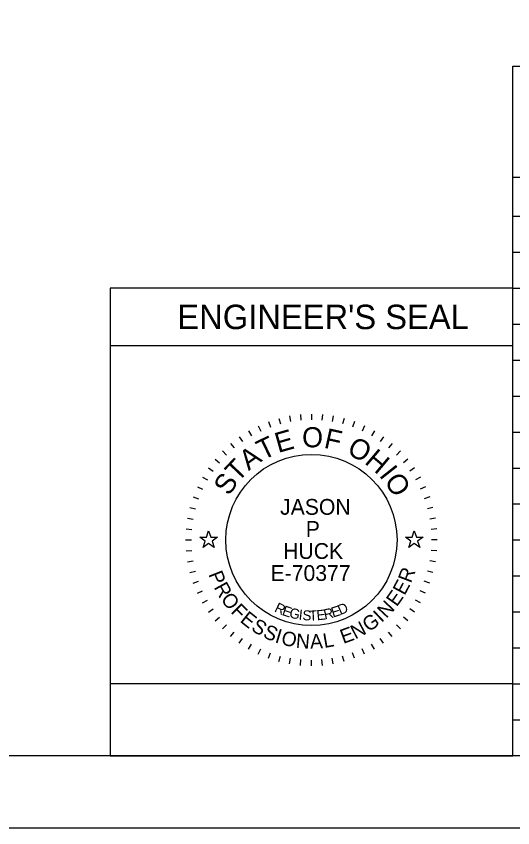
# Model space of a CAD drawing. Extents: x -1.8 to 75.7, y -2 to 25.
# Drawn here: x 48.4 to 51.85, y 1.61 to 7.25 of the extents above; entities that cross this region are included whole.
import ezdxf

# ---------------------------------------------------------------- set-up
doc = ezdxf.new("R2010")
doc.units = 0
for name, color, linetype in [('Default', 7, 'Continuous'), ('SH_Border', 7, 'Continuous'), ('SH_Cut_Line', 7, 'Continuous'), ('SH_Data', 7, 'Continuous')]:
    doc.layers.add(name, color=color, linetype=linetype)

msp = doc.modelspace()

# ---------------------------------------------------------------- linework, layer by layer
at = {"layer": 'Default'}
for points in [[(49.6738, 3.632), (49.7207, 3.632), (49.7352, 3.6766), (49.7497, 3.632), (49.7965, 3.632), (49.7587, 3.6045), (49.7731, 3.5599), (49.7352, 3.5874), (49.6972, 3.5599), (49.7117, 3.6045)], [(51.1038, 3.632), (51.1507, 3.632), (51.1652, 3.6766), (51.1797, 3.632), (51.2265, 3.632), (51.1887, 3.6045), (51.2031, 3.5599), (51.1652, 3.5874), (51.1272, 3.5599), (51.1417, 3.6045)]]:
    msp.add_lwpolyline(points, close=True, dxfattribs=at)
at = {"layer": 'SH_Border'}
msp.add_lwpolyline([(43.2002, 23.1121), (75.2002, 23.1121), (75.2002, 2.1121), (43.2002, 2.1121)], close=True, dxfattribs=at)
at = {"layer": 'SH_Cut_Line'}
msp.add_lwpolyline([(41.7002, 1.6121), (75.7002, 1.6121), (75.7002, 23.6121), (41.7002, 23.6121)], close=True, dxfattribs=at)
at = {"layer": 'SH_Data'}
for p, q in [((51.8502, 6.9038), (65.3002, 6.9038)), ((51.8502, 2.1121), (51.8502, 6.9038)), ((51.8502, 6.133), (65.3002, 6.133)), ((51.8502, 5.8621), (63.5752, 5.8621)), ((51.8502, 5.6121), (63.5752, 5.6121)), ((51.8502, 5.3621), (49.0502, 5.3621)), ((49.0502, 5.3621), (49.0502, 2.1121)), ((51.8502, 5.3621), (63.5752, 5.3621)), ((51.8502, 2.1121), (51.8502, 5.3621)), ((51.8502, 5.1121), (65.3002, 5.1121)), ((51.8502, 4.9621), (49.0502, 4.9621)), ((51.8502, 4.8621), (65.3002, 4.8621)), ((51.8502, 4.6121), (65.3002, 4.6121)), ((50.2237, 4.4573), (50.2341, 4.4186)), ((50.2982, 4.4738), (50.3052, 4.4344)), ((50.3739, 4.4838), (50.3774, 4.4439)), ((50.4502, 4.4871), (50.4502, 4.4471)), ((50.5264, 4.4838), (50.5229, 4.4439)), ((50.6021, 4.4738), (50.5952, 4.4344)), ((50.6766, 4.4573), (50.6663, 4.4186)), ((50.0804, 4.4051), (50.0973, 4.3688)), ((50.1509, 4.4343), (50.1646, 4.3967)), ((50.7494, 4.4343), (50.7358, 4.3967)), ((50.82, 4.4051), (50.8031, 4.3688)), ((50.0127, 4.3699), (50.0327, 4.3352)), ((50.8877, 4.3699), (50.8677, 4.3352)), ((51.8502, 4.3621), (65.3002, 4.3621)), ((49.9483, 4.3288), (49.9712, 4.2961)), ((50.952, 4.3288), (50.9291, 4.2961)), ((49.8314, 4.2308), (49.8597, 4.2025)), ((49.8877, 4.2824), (49.9134, 4.2517)), ((51.0126, 4.2824), (50.9869, 4.2517)), ((51.0689, 4.2308), (51.0406, 4.2025)), ((49.7799, 4.1745), (49.8105, 4.1488)), ((51.1205, 4.1745), (51.0898, 4.1488)), ((49.7334, 4.114), (49.7662, 4.091)), ((51.1669, 4.114), (51.1342, 4.091)), ((51.8502, 4.1121), (65.3002, 4.1121)), ((49.6924, 4.0496), (49.727, 4.0296)), ((51.2079, 4.0496), (51.1733, 4.0296)), ((49.6571, 3.9819), (49.6934, 3.965)), ((51.2432, 3.9819), (51.2069, 3.965)), ((49.6279, 3.9113), (49.6655, 3.8977)), ((51.2724, 3.9113), (51.2348, 3.8977)), ((49.605, 3.8385), (49.6436, 3.8282)), ((51.2954, 3.8385), (51.2567, 3.8282)), ((51.8502, 3.8621), (65.3002, 3.8621)), ((49.5885, 3.764), (49.6279, 3.7571)), ((51.3119, 3.764), (51.2725, 3.7571)), ((49.5785, 3.6883), (49.6183, 3.6849)), ((51.3218, 3.6883), (51.282, 3.6849)), ((49.5752, 3.6121), (49.6152, 3.6121)), ((51.3252, 3.6121), (51.2852, 3.6121)), ((51.8502, 3.6121), (65.3002, 3.6121)), ((49.5785, 3.5358), (49.6183, 3.5393)), ((51.3218, 3.5358), (51.282, 3.5393)), ((49.5885, 3.4601), (49.6279, 3.4671)), ((51.3119, 3.4601), (51.2725, 3.4671)), ((49.605, 3.3856), (49.6436, 3.396)), ((51.2954, 3.3856), (51.2567, 3.396)), ((51.8502, 3.3621), (65.3002, 3.3621)), ((49.6279, 3.3128), (49.6655, 3.3265)), ((51.2724, 3.3128), (51.2348, 3.3265)), ((49.6571, 3.2423), (49.6934, 3.2592)), ((51.2432, 3.2423), (51.2069, 3.2592)), ((49.6924, 3.1746), (49.727, 3.1946)), ((51.2079, 3.1746), (51.1733, 3.1946)), ((49.7334, 3.1102), (49.7662, 3.1331)), ((51.1669, 3.1102), (51.1342, 3.1331)), ((51.8502, 3.1121), (65.3002, 3.1121)), ((49.7799, 3.0496), (49.8105, 3.0754)), ((51.1205, 3.0496), (51.0898, 3.0754)), ((49.8314, 2.9934), (49.8597, 3.0216)), ((51.0689, 2.9934), (51.0406, 3.0216)), ((49.8877, 2.9418), (49.9134, 2.9724)), ((51.0126, 2.9418), (50.9869, 2.9724)), ((49.9483, 2.8953), (49.9712, 2.9281)), ((50.0127, 2.8543), (50.0327, 2.8889)), ((50.8877, 2.8543), (50.8677, 2.8889)), ((50.952, 2.8953), (50.9291, 2.9281)), ((50.0804, 2.8191), (50.0973, 2.8553)), ((50.1509, 2.7898), (50.1646, 2.8274)), ((50.7494, 2.7898), (50.7358, 2.8274)), ((50.82, 2.8191), (50.8031, 2.8553)), ((51.8502, 2.8621), (65.3002, 2.8621)), ((50.2237, 2.7669), (50.2341, 2.8055)), ((50.2982, 2.7504), (50.3052, 2.7898)), ((50.3739, 2.7404), (50.3774, 2.7803)), ((50.4502, 2.7371), (50.4502, 2.7771)), ((50.5264, 2.7404), (50.5229, 2.7803)), ((50.6021, 2.7504), (50.5952, 2.7898)), ((50.6766, 2.7669), (50.6663, 2.8055)), ((51.8502, 2.6121), (65.3002, 2.6121)), ((51.8502, 2.3621), (65.3002, 2.3621)), ((51.8502, 2.1121), (49.0502, 2.1121))]:
    msp.add_line(p, q, dxfattribs=at)
msp.add_lwpolyline([(51.8502, 2.1121), (51.8502, 2.6121), (49.0502, 2.6121), (49.0502, 2.1121)], close=True, dxfattribs=at)
msp.add_circle((50.4502, 3.6121), 0.595, dxfattribs=at)

# ---------------------------------------------------------------- texts
for s, height, p in [("ENGINEER'S SEAL", 0.17, (49.5177, 5.0771)), ('JASON', 0.11, (50.2323, 3.787)), ('P', 0.11, (50.4107, 3.6337)), ('HUCK', 0.11, (50.2537, 3.4804)), ('E-70377', 0.11, (50.1661, 3.3272))]:
    msp.add_text(s, height=height, dxfattribs=at).set_placement(p)
for s, height, rotation, p in [('E', 0.14, 15.7571, (50.2186, 4.2159)), ('O', 0.14, 359.7812, (50.3849, 4.2563)), ('F', 0.14, 347.4362, (50.5312, 4.2538)), ('T', 0.14, 25.7167, (50.1118, 4.1639)), ('O', 0.14, 332.2586, (50.69, 4.2136)), ('A', 0.14, 36.4747, (50.0136, 4.0902)), ('H', 0.14, 319.9136, (50.8133, 4.1482)), ('T', 0.14, 46.4344, (49.9385, 4.0085)), ('I', 0.14, 308.367, (50.9166, 4.0604)), ('S', 0.14, 57.1924, (49.8783, 3.9135)), ('O', 0.14, 303.1491, (50.9523, 4.0209)), ('P', 0.1, 291.494, (49.7324, 3.3741)), ('R', 0.1, 69.2322, (51.1421, 3.3075)), ('E', 0.1, 61.9951, (51.0978, 3.2219)), ('R', 0.1, 298.7311, (49.7691, 3.2838)), ('O', 0.1, 306.4666, (49.8156, 3.2004)), ('E', 0.1, 54.758, (51.0435, 3.1434)), ('F', 0.1, 314.7068, (49.8845, 3.1104)), ('R', 0.07, 334.487, (50.1877, 3.1171)), ('D', 0.07, 23.3052, (50.6512, 3.0891)), ('N', 0.1, 47.0224, (50.9704, 3.0629)), ('E', 0.1, 321.4393, (49.948, 3.0469)), ('E', 0.07, 341.04, (50.2408, 3.0921)), ('G', 0.07, 347.4752, (50.2916, 3.0739)), ('I', 0.07, 353.7858, (50.3592, 3.0589)), ('S', 0.07, 356.8926, (50.3859, 3.055)), ('T', 0.07, 3.0061, (50.4359, 3.0508)), ('E', 0.07, 6.0117, (50.4891, 3.0533)), ('R', 0.07, 11.9184, (50.5427, 3.0595)), ('E', 0.07, 17.6836, (50.6, 3.0723)), ('I', 0.1, 43.287, (50.937, 3.0335)), ('S', 0.1, 328.6764, (50.0245, 2.9873)), ('N', 0.1, 27.3113, (50.7546, 2.9196)), ('G', 0.1, 35.0469, (50.8482, 2.9691)), ('S', 0.1, 335.9134, (50.1066, 2.9387)), ('I', 0.1, 343.1505, (50.1908, 2.9018)), ('E', 0.1, 20.0742, (50.6714, 2.8891)), ('O', 0.1, 346.8859, (50.234, 2.8872)), ('N', 0.1, 355.1261, (50.339, 2.8638)), ('A', 0.1, 2.8617, (50.4424, 2.8558)), ('L', 0.1, 10.0987, (50.5396, 2.8611))]:
    msp.add_text(s, height=height, rotation=rotation, dxfattribs=at).set_placement(p)

doc.saveas('drawing.dxf')
